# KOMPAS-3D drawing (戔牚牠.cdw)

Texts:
  Стакан
  Ra 2.5
  Ra 1.25
  1. HRC  52...56
  2. Неуказанные радиусы 2мм max
  3. Неуказанные предельные отклонения размеров:
  H14, h14, IT14/2
  Ra 2,5
  Ra 6,3
  Ст.40X
  ГОСТ 4543-71
Dimensions and other numbers on the sheet: 130; 144; 100; 118; 37; 4; 3; 7; 0.01; 1; 0.002; 0.1; 0.012; 2; 5; 1:1; 0; 6; 8; 9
